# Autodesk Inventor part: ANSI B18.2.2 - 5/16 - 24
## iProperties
Created: 2005-03
Part Number: ANSI B18.2.2 - 5/16 - 24
Material: Steel, Mild
Description: Hex Jam Nut
Vendor: Autodesk Inc.
Document SubType Name: Modeling
Standard: ANSI B18.2.2
Designer: Admin
Standards Organization: ANSI
Language: en-US
Size Designation: 5/16 - 24
Categories: <MemberInstance Version="R10.0.0"><Categories><Category DisplayName="Fasteners" InternalName="e4da775c-781d-43d5-af7c-5136215cf5a6" Mnemonic="FSTN"><Category Di
Density: 1 g/cm^3
Author: Admin
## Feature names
1. Body [Extrusion]
2. Chamfer1 [Revolution]
3. Thread [Hole]
4. Chamfer2
5. Chamfer3
